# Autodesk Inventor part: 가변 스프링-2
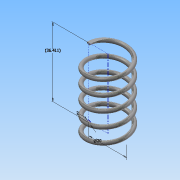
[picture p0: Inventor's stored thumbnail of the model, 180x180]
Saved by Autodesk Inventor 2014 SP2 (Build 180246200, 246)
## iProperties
Created: 2016-01
Part Number: 가변 스프링-2
Material: 스테인레스 스틸
Document SubType Name: Modeling
Designer: Administrator
Density: 8.08 g/cm^3
Appearance: 반연마
Mass: 7.88162 g
Surface Area: 19.7619 cm^2
Volume: 0.975448 cm^3
Author: Administrator
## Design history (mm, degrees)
sketch "스케치2"
  geometry: L1 (0, 0)-(10, 0); L2 (10, 0)-(10, 36.411); L3 (10, 36.411)-(0, 36.411); L4 (0, 36.411)-(0, 0); C1 r 1 at (10, 0)
  constraints: 8 end point, 2 parallel, 1 centre point, 1 coincident, 1 horizontal, 1 perpendicular
  dimensions: "d0" = 2 diameter of C1; "d1" = 20 diameter of L2 L4; "d2" = 36.4112 distance between parallel lines of L3 L1 (derived)
feature "코일1" pitch "d3" = 10; turns "d5" = 5; dims "d4" = 36.4112 (= d2), "d6" = 0, angle "d7" = 90 deg, angle "d8" = 90 deg, "d9" = 0, "d10" = 0
sketch "스케치3"
  geometry: L1 (-11, 0)-(-9, 0) reference; 1 further point
  constraints: 1 horizontal alignment
extrude "돌출1" cut sketch "스케치3" stored distance "d11" = 10; taper "d12" = 0 deg
node "작업 평면1"
sketch "스케치4"
  geometry: L1 (1, 0)-(-1, 0) reference; 1 further point
  constraints: 1 horizontal alignment
extrude "돌출2" cut sketch "스케치4" stored distance "d14" = 10; taper "d15" = 0 deg
node "솔리드1"
node "절단 모서리 투영1"
node "절단 모서리 투영2"
other parameters: "d13" = 0
